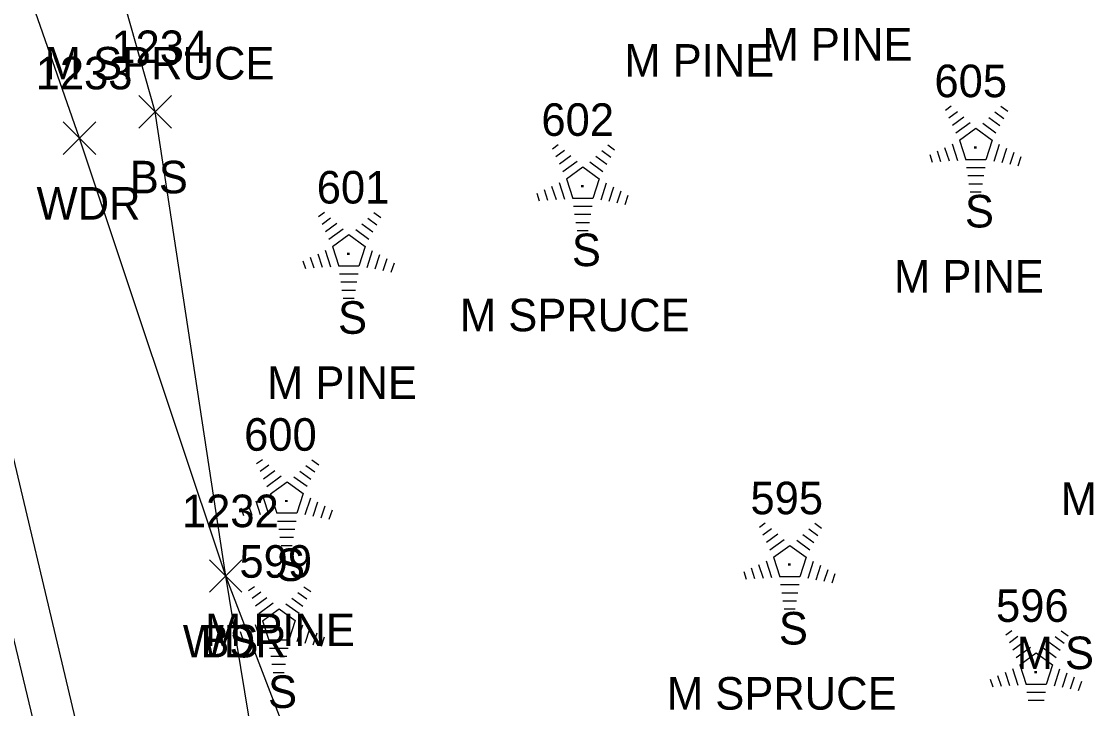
# Model space of a CAD drawing. Extents: x 1545627 to 1546562, y 571176 to 576667.
# Drawn here: x 1546152.2 to 1546217.9, y 572056.2 to 572098.5 of the extents above; entities that cross this region are included whole.
import ezdxf

# ---------------------------------------------------------------- set-up
doc = ezdxf.new("R2010")
doc.units = 0
for name, color, linetype in [('L_A', 7, 'Continuous'), ('L_C', 7, 'Continuous'), ('L_I', 7, 'Continuous'), ('L_TIC', 7, 'Continuous'), ('LAWA', 7, 'Continuous'), ('LELB', 7, 'Continuous'), ('LTC', 7, 'Continuous'), ('RGR', 7, 'Continuous')]:
    doc.layers.add(name, color=color, linetype=linetype)

msp = doc.modelspace()

# ---------------------------------------------------------------- linework, layer by layer
at = {"layer": 'L_TIC'}
for points in [[(1546159.424, 572091.892), (1546161.424, 572093.892)], [(1546161.424, 572091.892), (1546159.424, 572093.892)], [(1546154.771, 572090.279), (1546156.771, 572092.279)], [(1546156.771, 572090.279), (1546154.771, 572092.279)], [(1546163.758, 572063.391), (1546165.758, 572065.391)], [(1546165.758, 572063.391), (1546163.758, 572065.391)], [(1546163.758, 572063.391), (1546165.758, 572065.391)], [(1546165.758, 572063.391), (1546163.758, 572065.391)]]:
    msp.add_lwpolyline(points, dxfattribs=at)
at = {"layer": 'LAWA'}
msp.add_lwpolyline([(1546228.586, 571855.541), (1546209.815, 571899.546), (1546194.552, 571952.56), (1546185.852, 571982.338), (1546183.98, 571991.384), (1546179.112, 572029.569), (1546170.944, 572048.245), (1546164.758, 572064.391), (1546155.771, 572091.279), (1546144.336, 572123.946)], dxfattribs=at)
at = {"layer": 'LELB'}
for points in [[(1546347.404, 571535.241), (1546326.62, 571574.77), (1546309.351, 571609.13), (1546297.635, 571636.432), (1546292.788, 571646.222), (1546275.729, 571689.363), (1546263.627, 571715.111), (1546250.323, 571751.347), (1546233.4, 571797.155), (1546220.817, 571841.735), (1546218.613, 571853), (1546198.39, 571897.178), (1546185.101, 571947.883), (1546175.652, 571989.222), (1546174.94, 572003.263), (1546174.777, 572026.811), (1546167.554, 572047.439), (1546164.758, 572064.391), (1546160.424, 572092.892), (1546150.118, 572129.232)], [(1546346.375, 571534.64), (1546325.48, 571574.254), (1546308.892, 571608.63), (1546296.212, 571635.99), (1546273.967, 571687.639), (1546262.69, 571714.717), (1546248.75, 571750.385), (1546231.961, 571796.63), (1546217.305, 571838.705), (1546210.358, 571854.991), (1546196.649, 571896.999), (1546182.096, 571946.809), (1546169.64, 571995.561), (1546168.24, 572028.129), (1546158.043, 572044.974), (1546148.167, 572086.529), (1546140.639, 572120.601)]]:
    msp.add_lwpolyline(points, dxfattribs=at)
at = {"layer": 'LTC'}
for p, q in [((1546208.997, 572093.005), (1546209.351, 572093.263)), ((1546212.395, 572093.246), (1546212.814, 572092.941)), ((1546209.206, 572092.54), (1546209.736, 572092.924)), ((1546209.416, 572092.074), (1546210.12, 572092.585)), ((1546211.653, 572092.549), (1546212.332, 572092.055)), ((1546212.024, 572092.898), (1546212.573, 572092.498)), ((1546209.626, 572091.608), (1546210.504, 572092.246)), ((1546209.85, 572091.153), (1546210.862, 572091.888)), ((1546210.862, 572091.888), (1546211.859, 572091.163)), ((1546211.282, 572092.201), (1546212.091, 572091.612)), ((1546209.85, 572091.153), (1546210.237, 572089.96)), ((1546211.859, 572091.163), (1546211.468, 572089.96)), ((1546184.843, 572090.631), (1546185.197, 572090.888)), ((1546185.052, 572090.165), (1546185.582, 572090.549)), ((1546187.87, 572090.523), (1546188.419, 572090.123)), ((1546188.241, 572090.871), (1546188.66, 572090.566)), ((1546208.485, 572090.501), (1546208.696, 572089.85)), ((1546208.94, 572090.718), (1546209.211, 572089.883)), ((1546209.396, 572090.934), (1546209.726, 572089.915)), ((1546212.296, 572090.892), (1546211.958, 572089.853)), ((1546212.741, 572090.642), (1546212.453, 572089.757)), ((1546185.262, 572089.699), (1546185.966, 572090.211)), ((1546185.472, 572089.233), (1546186.35, 572089.871)), ((1546187.128, 572089.826), (1546187.937, 572089.237)), ((1546187.499, 572090.174), (1546188.178, 572089.681)), ((1546208.029, 572090.285), (1546208.181, 572089.817)), ((1546211.468, 572089.96), (1546210.237, 572089.96)), ((1546213.186, 572090.392), (1546212.948, 572089.662)), ((1546213.63, 572090.141), (1546213.443, 572089.567)), ((1546185.696, 572088.778), (1546186.708, 572089.513)), ((1546186.708, 572089.513), (1546187.705, 572088.788)), ((1546211.429, 572089.46), (1546210.285, 572089.46)), ((1546185.242, 572088.559), (1546185.572, 572087.54)), ((1546185.696, 572088.778), (1546186.083, 572087.585)), ((1546187.705, 572088.788), (1546187.314, 572087.585)), ((1546188.142, 572088.517), (1546187.804, 572087.478)), ((1546211.346, 572088.96), (1546210.357, 572088.96)), ((1546211.262, 572088.46), (1546210.43, 572088.46)), ((1546183.875, 572087.91), (1546184.027, 572087.442)), ((1546184.331, 572088.126), (1546184.542, 572087.475)), ((1546184.786, 572088.343), (1546185.057, 572087.508)), ((1546188.587, 572088.267), (1546188.299, 572087.382)), ((1546189.032, 572088.017), (1546188.794, 572087.287)), ((1546211.178, 572087.96), (1546210.503, 572087.96)), ((1546187.314, 572087.585), (1546186.083, 572087.585)), ((1546189.476, 572087.766), (1546189.289, 572087.192)), ((1546170.47, 572086.475), (1546170.824, 572086.733)), ((1546173.868, 572086.716), (1546174.287, 572086.411)), ((1546187.275, 572087.085), (1546186.131, 572087.085)), ((1546187.192, 572086.585), (1546186.203, 572086.585)), ((1546170.679, 572086.01), (1546171.208, 572086.394)), ((1546170.889, 572085.544), (1546171.593, 572086.055)), ((1546173.126, 572086.019), (1546173.805, 572085.525)), ((1546173.497, 572086.367), (1546174.046, 572085.968)), ((1546187.108, 572086.085), (1546186.276, 572086.085)), ((1546171.098, 572085.078), (1546171.977, 572085.716)), ((1546171.323, 572084.623), (1546172.335, 572085.358)), ((1546172.335, 572085.358), (1546173.332, 572084.633)), ((1546172.755, 572085.671), (1546173.564, 572085.082)), ((1546187.024, 572085.585), (1546186.349, 572085.585)), ((1546171.323, 572084.623), (1546171.71, 572083.43)), ((1546173.332, 572084.633), (1546172.941, 572083.43)), ((1546169.958, 572083.971), (1546170.169, 572083.319)), ((1546170.413, 572084.188), (1546170.684, 572083.352)), ((1546170.868, 572084.404), (1546171.199, 572083.385)), ((1546173.769, 572084.362), (1546173.431, 572083.322)), ((1546174.214, 572084.111), (1546173.926, 572083.227)), ((1546174.658, 572083.861), (1546174.421, 572083.132)), ((1546169.502, 572083.754), (1546169.654, 572083.286)), ((1546172.941, 572083.43), (1546171.71, 572083.43)), ((1546175.103, 572083.611), (1546174.916, 572083.037)), ((1546172.902, 572082.93), (1546171.758, 572082.93)), ((1546172.818, 572082.43), (1546171.83, 572082.43)), ((1546172.735, 572081.93), (1546171.903, 572081.93)), ((1546172.651, 572081.43), (1546171.976, 572081.43)), ((1546166.66, 572071.293), (1546167.015, 572071.551)), ((1546170.058, 572071.534), (1546170.477, 572071.229)), ((1546166.87, 572070.828), (1546167.399, 572071.212)), ((1546167.079, 572070.362), (1546167.783, 572070.873)), ((1546169.316, 572070.837), (1546169.995, 572070.343)), ((1546169.687, 572071.185), (1546170.237, 572070.786)), ((1546167.289, 572069.896), (1546168.167, 572070.534)), ((1546167.513, 572069.441), (1546168.525, 572070.176)), ((1546168.525, 572070.176), (1546169.522, 572069.451)), ((1546168.945, 572070.489), (1546169.755, 572069.9)), ((1546167.513, 572069.441), (1546167.9, 572068.248)), ((1546169.522, 572069.451), (1546169.131, 572068.248)), ((1546166.148, 572068.789), (1546166.36, 572068.138)), ((1546166.603, 572069.006), (1546166.875, 572068.17)), ((1546167.059, 572069.222), (1546167.39, 572068.203)), ((1546169.96, 572069.18), (1546169.622, 572068.14)), ((1546170.404, 572068.93), (1546170.117, 572068.045)), ((1546165.692, 572068.573), (1546165.845, 572068.105)), ((1546169.131, 572068.248), (1546167.9, 572068.248)), ((1546170.849, 572068.68), (1546170.612, 572067.95)), ((1546171.293, 572068.429), (1546171.106, 572067.855)), ((1546169.092, 572067.748), (1546167.948, 572067.748)), ((1546197.564, 572067.392), (1546197.919, 572067.649)), ((1546200.963, 572067.632), (1546201.382, 572067.328)), ((1546169.009, 572067.248), (1546168.02, 572067.248)), ((1546197.774, 572066.926), (1546198.303, 572067.311)), ((1546197.983, 572066.461), (1546198.687, 572066.972)), ((1546200.22, 572066.936), (1546200.9, 572066.442)), ((1546200.591, 572067.284), (1546201.141, 572066.885)), ((1546168.925, 572066.748), (1546168.093, 572066.748)), ((1546168.841, 572066.248), (1546168.166, 572066.248)), ((1546198.193, 572065.995), (1546199.071, 572066.633)), ((1546198.418, 572065.54), (1546199.429, 572066.274)), ((1546199.429, 572066.274), (1546200.426, 572065.549)), ((1546199.849, 572066.587), (1546200.659, 572065.999)), ((1546198.418, 572065.54), (1546198.805, 572064.347)), ((1546200.426, 572065.549), (1546200.035, 572064.347)), ((1546197.052, 572064.888), (1546197.264, 572064.236)), ((1546197.508, 572065.104), (1546197.779, 572064.269)), ((1546197.963, 572065.321), (1546198.294, 572064.302)), ((1546200.864, 572065.279), (1546200.526, 572064.239)), ((1546201.308, 572065.028), (1546201.021, 572064.144)), ((1546196.597, 572064.671), (1546196.749, 572064.203)), ((1546200.035, 572064.347), (1546198.805, 572064.347)), ((1546201.753, 572064.778), (1546201.516, 572064.049)), ((1546202.197, 572064.528), (1546202.01, 572063.954)), ((1546166.169, 572063.494), (1546166.524, 572063.751)), ((1546169.568, 572063.734), (1546169.987, 572063.43)), ((1546199.997, 572063.847), (1546198.852, 572063.847)), ((1546166.379, 572063.028), (1546166.908, 572063.413)), ((1546166.588, 572062.563), (1546167.292, 572063.074)), ((1546168.826, 572063.038), (1546169.505, 572062.544)), ((1546169.196, 572063.386), (1546169.746, 572062.987)), ((1546199.913, 572063.347), (1546198.925, 572063.347)), ((1546166.798, 572062.097), (1546167.676, 572062.735)), ((1546167.023, 572061.642), (1546168.034, 572062.376)), ((1546168.034, 572062.376), (1546169.031, 572061.651)), ((1546168.454, 572062.689), (1546169.264, 572062.1)), ((1546199.829, 572062.847), (1546198.998, 572062.847)), ((1546199.746, 572062.347), (1546199.071, 572062.347)), ((1546167.023, 572061.642), (1546167.41, 572060.448)), ((1546169.031, 572061.651), (1546168.64, 572060.448)), ((1546165.657, 572060.99), (1546165.869, 572060.338)), ((1546166.113, 572061.206), (1546166.384, 572060.371)), ((1546166.568, 572061.423), (1546166.899, 572060.403)), ((1546169.469, 572061.38), (1546169.131, 572060.341)), ((1546169.913, 572061.13), (1546169.626, 572060.245)), ((1546212.709, 572060.782), (1546213.064, 572061.04)), ((1546216.108, 572061.023), (1546216.527, 572060.718)), ((1546165.202, 572060.773), (1546165.354, 572060.305)), ((1546168.64, 572060.448), (1546167.41, 572060.448)), ((1546170.358, 572060.88), (1546170.121, 572060.15)), ((1546170.802, 572060.63), (1546170.616, 572060.055)), ((1546212.919, 572060.317), (1546213.448, 572060.701)), ((1546213.128, 572059.851), (1546213.832, 572060.362)), ((1546215.365, 572060.326), (1546216.045, 572059.832)), ((1546215.736, 572060.674), (1546216.286, 572060.275)), ((1546168.602, 572059.948), (1546167.457, 572059.948)), ((1546213.338, 572059.385), (1546214.216, 572060.023)), ((1546213.563, 572058.93), (1546214.574, 572059.665)), ((1546214.574, 572059.665), (1546215.571, 572058.94)), ((1546214.994, 572059.978), (1546215.804, 572059.389)), ((1546168.518, 572059.448), (1546167.53, 572059.448)), ((1546168.434, 572058.948), (1546167.603, 572058.948)), ((1546213.563, 572058.93), (1546213.95, 572057.737)), ((1546215.571, 572058.94), (1546215.18, 572057.737)), ((1546168.351, 572058.448), (1546167.676, 572058.448)), ((1546212.197, 572058.278), (1546212.409, 572057.627)), ((1546212.653, 572058.495), (1546212.924, 572057.659)), ((1546213.108, 572058.711), (1546213.439, 572057.692)), ((1546216.009, 572058.669), (1546215.671, 572057.629)), ((1546216.453, 572058.419), (1546216.166, 572057.534)), ((1546211.742, 572058.062), (1546211.894, 572057.594)), ((1546215.18, 572057.737), (1546213.95, 572057.737)), ((1546216.898, 572058.169), (1546216.661, 572057.439)), ((1546217.342, 572057.918), (1546217.155, 572057.344)), ((1546215.142, 572057.237), (1546213.997, 572057.237)), ((1546215.058, 572056.737), (1546214.07, 572056.737))]:
    msp.add_line(p, q, dxfattribs=at)
at = {"layer": 'RGR'}
msp.add_lwpolyline([(1546165.414, 572025.193), (1546158.523, 572036.45), (1546155.575, 572044.541), (1546145.635, 572085.932), (1546137.816, 572118.618)], dxfattribs=at)

# ---------------------------------------------------------------- texts
at = {"layer": 'L_A'}
for s, p in [('BS', (1546158.865, 572087.892)), ('WDR', (1546153.133, 572086.279)), ('S', (1546210.187, 572085.797)), ('S', (1546186.033, 572083.422)), ('S', (1546171.66, 572079.267)), ('S', (1546167.851, 572064.085)), ('S', (1546198.755, 572060.184)), ('WDR', (1546162.12, 572059.391)), ('BS', (1546163.199, 572059.391)), ('S', (1546167.36, 572056.286))]:
    msp.add_text(s, height=2, dxfattribs=at).set_placement(p)
at = {"layer": 'L_C'}
for s, p in [('M PINE', (1546197.747, 572096.051)), ('M PINE', (1546189.255, 572095.056)), ('M SPRUCE', (1546153.637, 572094.885)), ('M PINE', (1546205.825, 572081.797)), ('M SPRUCE', (1546179.152, 572079.422)), ('M PINE', (1546167.298, 572075.267)), ('M PINE', (1546216.071, 572068.147)), ('M PINE', (1546163.488, 572060.085)), ('M SPRUCE', (1546213.365, 572058.671)), ('M SPRUCE', (1546191.873, 572056.184))]:
    msp.add_text(s, height=2, dxfattribs=at).set_placement(p)
at = {"layer": 'L_I'}
for s, p in [('1234', (1546157.731, 572095.892)), ('1233', (1546153.078, 572094.279)), ('605', (1546208.313, 572093.797)), ('602', (1546184.159, 572091.422)), ('601', (1546170.353, 572087.267)), ('600', (1546165.89, 572072.085)), ('595', (1546197.007, 572068.184)), ('1232', (1546162.065, 572067.391)), ('1232', (1546162.065, 572067.391)), ('599', (1546165.604, 572064.286)), ('596', (1546212.097, 572061.574))]:
    msp.add_text(s, height=2, dxfattribs=at).set_placement(p)
at = {"layer": 'LTC'}
for p in [(1546210.744, 572090.901), (1546186.59, 572088.526), (1546172.217, 572084.371), (1546168.407, 572069.189), (1546199.312, 572065.288), (1546167.917, 572061.39), (1546214.457, 572058.678)]:
    msp.add_text('.', height=1.037, rotation=270, dxfattribs=at).set_placement(p)

doc.saveas('drawing.dxf')
